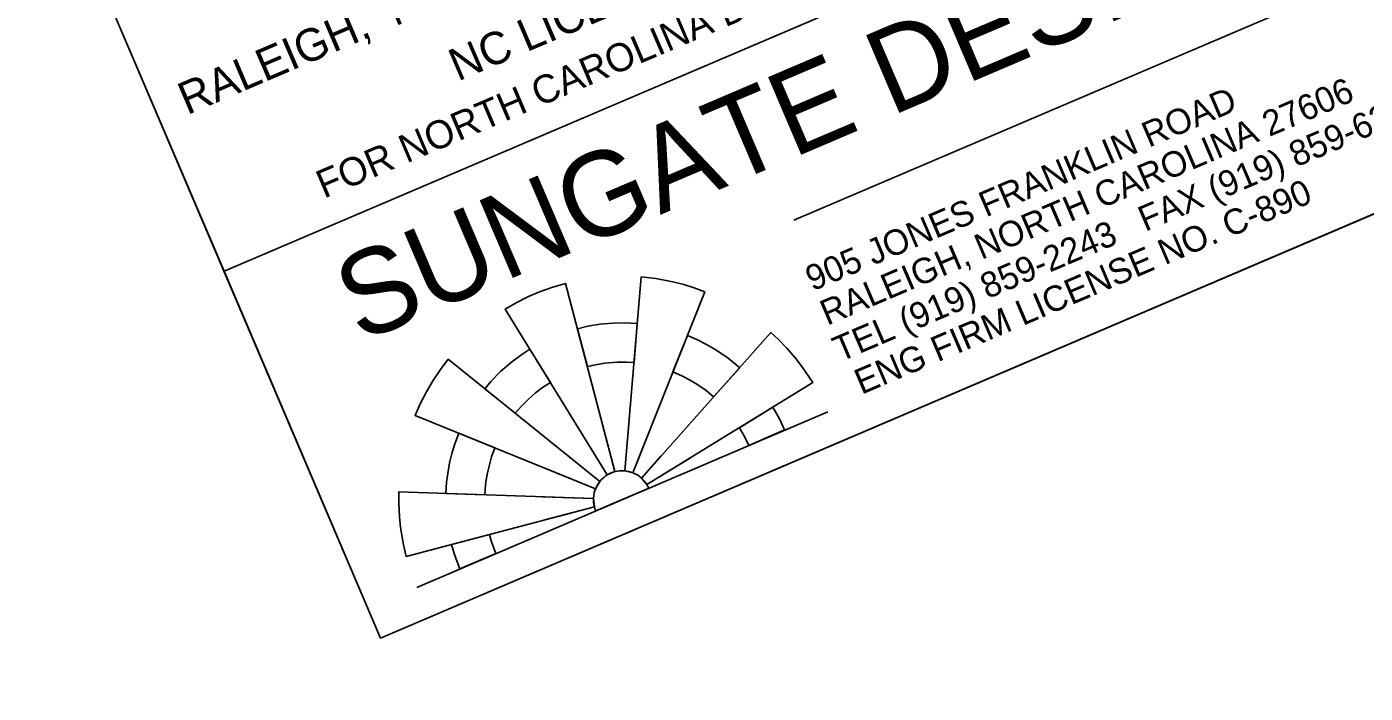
# Model space of a CAD drawing. Extents: x 2192740 to 2194721, y 86011 to 87688.
# Drawn here: x 2193973 to 2194120.8, y 87432.2 to 87505.7 of the extents above; entities that cross this region are included whole.
import ezdxf

# ---------------------------------------------------------------- set-up
doc = ezdxf.new("R2010")
doc.units = 0
for name, color, linetype in [('Exist Other Culture Sign', 7, 'Continuous'), ('Exist Right of Way Monument CELL', 7, 'Continuous'), ('Exist Utilities Other Traffic Signal Box CELL', 7, 'Continuous')]:
    doc.layers.add(name, color=color, linetype=linetype)

msp = doc.modelspace()

# ---------------------------------------------------------------- linework, layer by layer
at = {"layer": 'Exist Other Culture Sign'}
for p, q in [((2194057.71, 87484.36), (2194119.79, 87510.87)), ((2194040.05, 87468.68), (2194040.05, 87468.68)), ((2194016.07, 87443.84), (2194061.46, 87463.22)), ((2194026.98, 87463.1), (2194026.98, 87463.1)), ((2194037.96, 87456.62), (2194036.52, 87462.08)), ((2194039.03, 87456.71), (2194039.52, 87462.34)), ((2194042.02, 87461.75), (2194039.94, 87456.5)), ((2194037.1, 87456.25), (2194034.14, 87461.06)), ((2194036.28, 87455.53), (2194031.89, 87459.08)), ((2194040.88, 87455.91), (2194044.64, 87460.13)), ((2194043.05, 87458.35), (2194040.88, 87455.91)), ((2194041.48, 87455.2), (2194046.29, 87458.16)), ((2194030.58, 87456.86), (2194035.81, 87454.73)), ((2194035.58, 87453.65), (2194029.94, 87453.85)), ((2194031.47, 87453.81), (2194031.47, 87453.81)), ((2194035.68, 87452.72), (2194030.22, 87451.3)), ((2194021.89, 87449.1), (2194021.89, 87449.1))]:
    msp.add_line(p, q, dxfattribs=at)
for points in [[(2193994.8, 87478.73), (2194118.41, 87531.51), (2194135.69, 87491.03), (2194012.09, 87438.25)], [(2194039.03, 87456.71), (2194040.86, 87478.12), (2194042.48, 87477.93), (2194044.34, 87477.57), (2194045.55, 87477.26), (2194046.71, 87476.9), (2194047.86, 87476.47), (2194039.94, 87456.5)], [(2194037.1, 87456.25), (2194025.85, 87474.57), (2194027.05, 87475.25), (2194028.42, 87475.94), (2194029.61, 87476.45), (2194031.1, 87476.99), (2194032.5, 87477.4), (2194037.96, 87456.62)], [(2194033.82, 87472.39), (2194034.98, 87472.66), (2194036.33, 87472.88), (2194037.72, 87473), (2194039.02, 87473.03), (2194040.42, 87472.96), (2194040.06, 87468.65), (2194039.25, 87468.7), (2194038.22, 87468.7), (2194036.79, 87468.58), (2194035.81, 87468.42), (2194034.91, 87468.21)], [(2194040.88, 87455.89), (2194055.18, 87471.96), (2194056.01, 87471.19), (2194056.93, 87470.24), (2194057.89, 87469.13), (2194058.6, 87468.21), (2194059.8, 87466.44), (2194041.48, 87455.2)], [(2194045.95, 87471.65), (2194047, 87471.2), (2194048.07, 87470.66), (2194049.09, 87470.07), (2194050.44, 87469.15), (2194051.73, 87468.09), (2194048.85, 87464.86), (2194048.02, 87465.56), (2194046.98, 87466.29), (2194046.18, 87466.77), (2194045.43, 87467.16), (2194044.36, 87467.64)], [(2194023.59, 87465.77), (2194024.26, 87466.56), (2194025.33, 87467.66), (2194026.53, 87468.71), (2194027.66, 87469.56), (2194028.57, 87470.15), (2194030.83, 87466.46), (2194029.97, 87465.9), (2194029.19, 87465.3), (2194028.42, 87464.63), (2194027.63, 87463.84), (2194026.95, 87463.06)], [(2194035.81, 87454.73), (2194015.9, 87462.82), (2194016.47, 87464.1), (2194017.14, 87465.43), (2194017.86, 87466.64), (2194018.69, 87467.89), (2194019.55, 87469.02), (2194036.28, 87455.53)], [(2194055.38, 87463.73), (2194056.11, 87462.43), (2194056.68, 87461.22), (2194052.72, 87459.49), (2194052.24, 87460.49), (2194051.69, 87461.47)], [(2194019.28, 87454.22), (2194019.36, 87455.44), (2194019.49, 87456.41), (2194019.69, 87457.58), (2194019.95, 87458.62), (2194020.27, 87459.68), (2194020.71, 87460.87), (2194024.71, 87459.25), (2194024.34, 87458.24), (2194024.09, 87457.38), (2194023.88, 87456.49), (2194023.72, 87455.5), (2194023.64, 87454.73), (2194023.6, 87454.06)], [(2194035.83, 87452.28), (2194035.75, 87452.51), (2194035.68, 87452.72), (2194035.59, 87453.23), (2194035.58, 87453.65), (2194035.61, 87453.97), (2194035.67, 87454.28), (2194035.74, 87454.54), (2194035.81, 87454.73), (2194036.02, 87455.16), (2194036.28, 87455.53), (2194036.48, 87455.75), (2194036.71, 87455.97), (2194036.93, 87456.14), (2194037.1, 87456.25), (2194037.52, 87456.47), (2194037.96, 87456.62), (2194038.23, 87456.68), (2194038.47, 87456.71), (2194038.73, 87456.72), (2194039.03, 87456.71), (2194039.49, 87456.64), (2194039.94, 87456.5), (2194040.17, 87456.39), (2194040.43, 87456.25), (2194040.63, 87456.11), (2194040.88, 87455.91), (2194041.23, 87455.56), (2194041.48, 87455.2), (2194041.6, 87454.99), (2194041.69, 87454.79)], [(2194035.68, 87452.72), (2194014.9, 87447.27), (2194014.6, 87448.54), (2194014.28, 87450.44), (2194014.16, 87451.64), (2194014.09, 87453.21), (2194014.1, 87454.4), (2194035.58, 87453.65)], [(2194020.84, 87445.88), (2194020.52, 87446.67), (2194020.2, 87447.6), (2194019.91, 87448.58), (2194024.09, 87449.68), (2194024.3, 87448.98), (2194024.54, 87448.28), (2194024.82, 87447.58)]]:
    msp.add_lwpolyline(points, close=True, dxfattribs=at)
for start, end in [(23.1206, 203.1206), (203.1206, 23.1206)]:
    msp.add_arc((2194091.86, 87482.75), 0.138, start, end, dxfattribs=at)
at = {"layer": 'Exist Right of Way Monument CELL'}
for p, q in [((2194118.41, 87531.51), (2193994.8, 87478.73)), ((2193994.8, 87478.73), (2193975.79, 87523.27))]:
    msp.add_line(p, q, dxfattribs=at)
at = {"layer": 'Exist Utilities Other Traffic Signal Box CELL'}
msp.add_lwpolyline([(2194135.69, 87491.03), (2194167.54, 87416.43), (2194338.24, 87489.32), (2194682.39, 86683.26), (2193316.15, 86099.93), (2193239.14, 86280.31), (2193214.47, 87198.22), (2193975.79, 87523.27), (2194012.09, 87438.25)], close=True, dxfattribs=at)

# ---------------------------------------------------------------- texts
at = {"layer": 'Exist Other Culture Sign'}
for s, height, p in [('SUNGATE DESIGN GROUP, P.A.', 9.3194, (2194009.82, 87470.8)), ('905 JONES FRANKLIN ROAD', 2.8007, (2194059.76, 87476.5)), ('RALEIGH, NORTH CAROLINA 27606', 2.8007, (2194061.38, 87472.71)), ('TEL (919) 859-2243   FAX (919) 859-6258', 2.8007, (2194062.79, 87468.69)), ('ENG FIRM LICENSE NO. C-890', 2.8007, (2194065.17, 87465.09))]:
    msp.add_text(s, height=height, rotation=23.1206, dxfattribs=at).set_placement(p)
at = {"layer": 'Exist Right of Way Monument CELL'}
for s, height, p in [('RALEIGH,  NORTH CAROLINA, (919) 854-1345', 3.5754, (2193990.73, 87495.95)), ('FOR NORTH CAROLINA DEPT. OF TRANSPORTATION', 3.1013, (2194005.84, 87486.73)), ('NC LICENSE NO. F-0246', 3.5754, (2194020.62, 87499.66))]:
    msp.add_text(s, height=height, rotation=23.1206, dxfattribs=at).set_placement(p)

doc.saveas('drawing.dxf')
